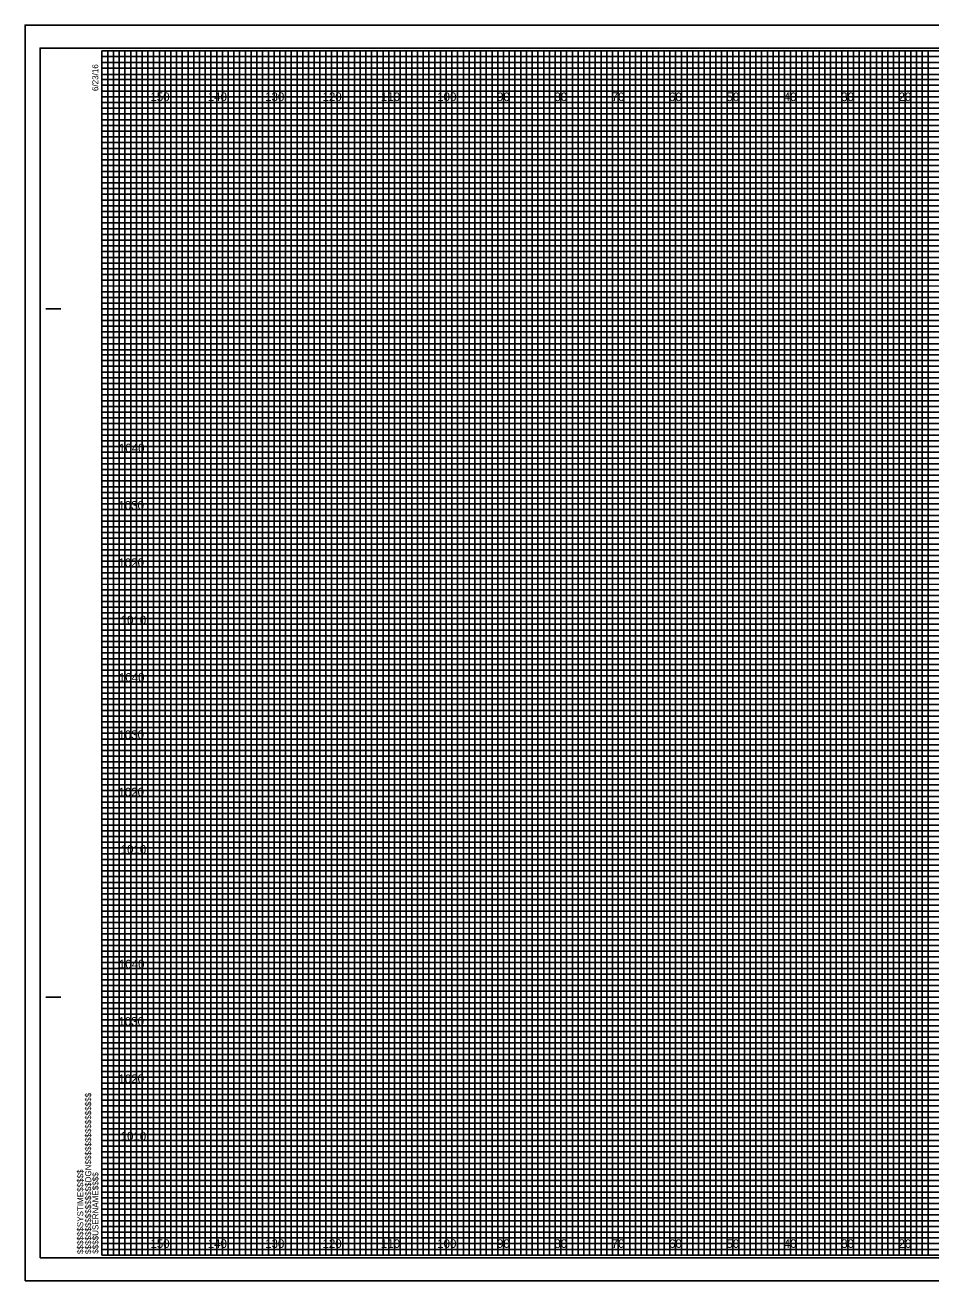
# Model space of a CAD drawing. Extents: x -13 to 323, y -5 to 215.
# Drawn here: x -13.4 to 144.5, y -4.5 to 214.5 of the extents above; entities that cross this region are included whole.
import ezdxf

# ---------------------------------------------------------------- set-up
doc = ezdxf.new("R2010")
doc.units = 0
for name, color, linetype in [('Prop XS Elevation Labels', 7, 'Continuous'), ('Prop XS Offset Labels', 7, 'Continuous'), ('Sheet Cross Section CELL', 7, 'Continuous'), ('Sheet Cross Section Grid Major CELL', 7, 'Continuous'), ('Sheet Cross Section Grid Middle CELL', 7, 'Continuous'), ('Sheet Cross Section Grid Minor 1 CELL', 7, 'Continuous'), ('Sheet Cross Section Grid Minor 2 CELL', 7, 'Continuous'), ('Sheet Cutting Line CELL', 7, 'Continuous'), ('Sheet DOT Grid CELL', 7, 'Continuous'), ('Sheet Plot Border Inside CELL', 7, 'Continuous'), ('Sheet Plot Border Outside CELL', 7, 'Continuous')]:
    doc.layers.add(name, color=color, linetype=linetype)

msp = doc.modelspace()

# ---------------------------------------------------------------- linework, layer by layer
at = {"layer": 'Sheet Cross Section CELL'}
for p, q in [((-9.8, 165), (-7.3, 165)), ((-9.7, 165), (-7.2, 165)), ((-9.8, 45), (-7.3, 45)), ((-9.7, 45), (-7.2, 45)), ((0, 0), (0, 0)), ((0, 0), (0, 0)), ((0, 0), (0, 0)), ((0, 0), (0, 0)), ((0, 0), (0, 0)), ((0, 0), (0, 0)), ((0, 0), (0, 0))]:
    msp.add_line(p, q, dxfattribs=at)
msp.add_lwpolyline([(320, 210), (0, 210), (0, 0), (320, 0)], close=True, dxfattribs=at)
at = {"layer": 'Sheet Cross Section Grid Major CELL'}
for p, q in [((10, 210), (0, 210)), ((10, 0), (10, 210)), ((30, 210), (20, 210)), ((20, 210), (20, 0)), ((30, 0), (30, 210)), ((50, 210), (40, 210)), ((40, 210), (40, 0)), ((50, 0), (50, 210)), ((70, 210), (60, 210)), ((60, 210), (60, 0)), ((70, 0), (70, 210)), ((90, 210), (80, 210)), ((80, 210), (80, 0)), ((90, 0), (90, 210)), ((110, 210), (100, 210)), ((100, 210), (100, 0)), ((110, 0), (110, 210)), ((130, 210), (120, 210)), ((120, 210), (120, 0)), ((130, 0), (130, 210)), ((150, 210), (140, 210)), ((140, 210), (140, 0)), ((20, 0), (10, 0)), ((40, 0), (30, 0)), ((60, 0), (50, 0)), ((80, 0), (70, 0)), ((100, 0), (90, 0)), ((120, 0), (110, 0)), ((140, 0), (130, 0))]:
    msp.add_line(p, q, dxfattribs=at)
for points in [[(0, 200), (320, 200), (320, 190), (0, 190)], [(0, 180), (320, 180), (320, 170), (0, 170)], [(0, 160), (320, 160), (320, 150), (0, 150)], [(0, 140), (320, 140), (320, 130), (0, 130)], [(0, 120), (320, 120), (320, 110), (0, 110)], [(0, 100), (320, 100), (320, 90), (0, 90)], [(0, 80), (320, 80), (320, 70), (0, 70)], [(0, 60), (320, 60), (320, 50), (0, 50)], [(0, 40), (320, 40), (320, 30), (0, 30)], [(0, 20), (320, 20), (320, 10), (0, 10)]]:
    msp.add_lwpolyline(points, dxfattribs=at)
at = {"layer": 'Sheet Cross Section Grid Middle CELL'}
for points in [[(0, 210), (5, 210), (5, 0), (15, 0), (15, 210), (25, 210), (25, 0), (35, 0), (35, 210), (45, 210), (45, 0), (55, 0), (55, 210), (65, 210), (65, 0), (75, 0), (75, 210), (85, 210), (85, 0), (95, 0), (95, 210), (105, 210), (105, 0), (115, 0), (115, 210), (125, 210), (125, 0), (135, 0), (135, 210), (145, 210)], [(0, 205), (275, 205)], [(0, 185), (320, 185), (320, 195), (0, 195)], [(0, 165), (320, 165), (320, 175), (0, 175)], [(0, 145), (320, 145), (320, 155), (0, 155)], [(0, 125), (320, 125), (320, 135), (0, 135)], [(0, 105), (320, 105), (320, 115), (0, 115)], [(0, 85), (320, 85), (320, 95), (0, 95)], [(0, 65), (320, 65), (320, 75), (0, 75)], [(0, 45), (320, 45), (320, 55), (0, 55)], [(0, 25), (320, 25), (320, 35), (0, 35)], [(0, 5), (320, 5), (320, 15), (0, 15)]]:
    msp.add_lwpolyline(points, dxfattribs=at)
at = {"layer": 'Sheet Cross Section Grid Minor 1 CELL'}
for p, q in [((0, 209), (260, 209)), ((260, 207.98), (0, 207.98)), ((0, 207.98), (0, 207)), ((0, 207), (260, 207)), ((260, 205.89), (0, 205.89)), ((0, 205.89), (0, 204)), ((0, 204), (320, 204))]:
    msp.add_line(p, q, dxfattribs=at)
for points in [[(0, 203), (270, 203), (320, 203), (320, 202), (0, 202)], [(0, 201), (320, 201), (320, 199), (0, 199)], [(0, 198), (320, 198), (320, 197), (0, 196.98)], [(0, 196), (320, 196), (320, 194), (0, 194)], [(0, 193), (320, 193), (320, 192), (0, 192)], [(0, 191), (320, 191), (320, 189), (0, 189)], [(0, 188), (320, 188), (320, 187), (0, 187)], [(0, 186), (320, 186), (320, 184), (0, 184)], [(0, 183), (320, 183), (320, 182), (0, 182)], [(0, 181), (320, 181), (320, 179), (0, 179)], [(0, 178), (320, 178), (320, 177), (0, 177)], [(0, 176), (320, 176), (320, 173.95), (320, 173), (320, 172), (0, 172)], [(0, 174), (320, 174), (320, 173), (0, 173)], [(0, 171), (320, 171), (320, 169), (0, 169.03)], [(0, 169.03), (320, 169), (320, 168), (0, 168)], [(0, 167), (320, 167), (320, 166), (0, 166)], [(0, 164), (320, 164), (320, 163), (0, 163)], [(0, 162), (320, 162), (320, 161), (0, 161)], [(-0.07, 158.89), (320, 158.89), (320, 157.88), (-0.07, 157.88)], [(0, 157), (320, 157), (320, 156), (0, 156)], [(0, 154), (320, 154), (320, 153), (0, 153)], [(0, 152), (320, 152), (320, 151), (0, 151)], [(0, 149), (320, 149), (320, 148), (0, 148)], [(0, 147), (320, 147), (320, 146), (0, 146)], [(0, 144), (320, 144), (320, 143), (0, 143)], [(0, 142), (320, 142), (320, 141), (0, 141)], [(0, 139), (320, 139), (319.99, 137.98), (0, 138)], [(0, 137), (320, 137), (320, 136), (0, 136)], [(0, 134), (320, 134), (320, 133), (0, 133)], [(0, 132), (320, 132), (320, 131), (0, 131)], [(0, 129), (320, 129), (320, 128), (0, 128)], [(0, 127), (320, 127), (320, 126), (0, 126)], [(0, 124), (320, 124), (320, 123), (0, 123)], [(0, 122), (320, 122), (320, 121), (0, 121)], [(0, 119), (320, 119), (320, 118), (0, 118)], [(0, 116.99), (320.07, 116.91), (320, 116), (0, 116)], [(0, 114), (320, 114), (320, 113), (0, 113)], [(0, 112), (320, 112), (320, 111), (0, 111)], [(0, 109), (320, 109), (320, 108), (0, 108)], [(0, 107), (320, 107), (320, 106), (0, 106)], [(0, 104), (320, 104), (320, 103), (0, 103)], [(0, 102), (320, 102), (320, 101), (0, 101)], [(0, 99), (320, 99), (320, 98), (0, 98)], [(0, 97), (320, 97), (320, 96), (0, 96)], [(0, 94), (320, 94), (320, 93), (0, 93)], [(0, 92), (320, 92), (320, 91), (0, 91)], [(0, 89), (320, 89), (320, 88), (0, 88)], [(0, 87), (320, 87), (320, 86), (0, 86)], [(0, 84), (320, 84), (320, 83), (0, 83)], [(0, 82), (320, 82), (320, 81), (0, 81)], [(0, 79), (320, 79), (319.99, 77.98), (0, 78)], [(0, 77), (320, 77), (320, 76), (0, 76)], [(0, 74), (320, 74), (320, 73), (0, 73)], [(0, 72), (320, 72), (320, 71), (0, 71)], [(0, 69), (320, 69), (320, 68), (0, 68)], [(0, 67), (320, 67), (320, 66), (0, 66)], [(0, 64), (320, 64), (320, 63), (0, 63)], [(0, 62), (320, 62), (320, 61), (0, 61)], [(0, 59), (320, 59), (320, 58), (0, 58)], [(0, 56.99), (320.07, 56.91), (320, 56), (0, 56)], [(0, 54), (320, 54), (320, 53), (0, 53)], [(0, 52), (320, 52), (320, 51), (0, 51)], [(0, 49), (320, 49), (320, 48), (0, 48)], [(0, 47), (320, 47), (320, 46), (0, 46)], [(0, 44), (320, 44), (320, 43), (0, 43)], [(0, 42), (320, 42), (320, 41), (0, 41)], [(0, 39), (320, 39), (320, 38), (0, 38)], [(0, 37), (320, 37), (320, 36), (0, 36)], [(0, 34), (320, 34), (320, 33), (0, 33)], [(0, 32), (320, 32), (320, 31), (0, 31)], [(0, 29), (320, 29), (320, 28), (0, 28)], [(0, 27), (320, 27), (320, 26), (0, 26)], [(0, 24), (320, 24), (320, 23), (0, 23)], [(0, 22), (320, 22), (320, 21), (0, 21)], [(0, 19), (320, 19), (320, 18), (0, 18)], [(0, 17), (320, 17), (320, 16), (0, 16)], [(0, 14), (320, 14), (320, 13), (0, 13)], [(0, 12), (320, 12), (320, 11), (0, 11)], [(0, 9), (320, 9), (320, 8), (0, 8)], [(0, 7), (320, 7), (320, 6), (0, 6)], [(0, 4), (320, 4), (320, 3), (0, 3)], [(0, 2), (320, 2), (320, 1), (0, 1)]]:
    msp.add_lwpolyline(points, dxfattribs=at)
at = {"layer": 'Sheet Cross Section Grid Minor 2 CELL'}
for points in [[(0, 0), (1, 0), (1, 210), (2, 210), (2, 0)], [(2, 0), (3, 0), (3, 210), (4, 210), (4, 0)], [(5, 0), (6, 0), (6, 210), (7, 210), (7, 0)], [(7, 0), (8, 0), (8, 210), (9, 210), (9, 0)], [(10, 0), (11, 0), (11, 210), (12, 210), (12, 0)], [(12, 0), (13, 0), (13, 210), (14, 210), (14, 0)], [(15, 0), (16, 0), (16, 210), (17, 210), (17, 0)], [(17, 0), (18, 0), (18, 210), (19, 210), (19, 0)], [(20, 0), (21, 0), (21, 210), (22, 210), (22, 0)], [(22, 0), (23, 0), (23, 210), (24, 210), (24, 0)], [(25, 0), (26, 0), (26, 210), (27, 210), (27, 0)], [(27, 0), (28, 0), (28, 210), (29, 210), (29, 0)], [(30, 0), (31, 0), (31, 210), (32, 210), (32, 0)], [(32, 0), (33, 0), (33, 210), (34, 210), (34, 0)], [(35, 0), (36, 0), (36, 210), (37, 210), (37, 0)], [(37, 0), (38, 0), (38, 210), (39, 210), (39, 0)], [(40, 0), (41, 0), (41, 210), (42, 210), (42, 0)], [(42, 0), (43, 0), (43, 210), (44, 210), (44, 0)], [(45, 0), (46, 0), (46, 210), (47, 210), (47, 0)], [(47, 0), (48, 0), (48, 210), (49, 210), (49, 0)], [(50, 0), (51, 0), (51, 210), (52, 210), (52, 0)], [(52, 0), (53, 0), (53, 210), (54, 210), (54, 0)], [(55, 0), (56, 0), (56, 210), (57, 210), (57, 0)], [(57, 0), (58, 0), (58, 210), (59, 210), (59, 0)], [(60, 0), (61, 0), (61, 210), (62, 210), (62, 0)], [(62, 0), (63, 0), (63, 210), (64, 210), (64, 0)], [(65, 0), (66, 0), (66, 210), (67, 210), (67, 0)], [(67, 0), (68, 0), (68, 210), (69, 210), (69, 0)], [(70, 0), (71, 0), (71, 210), (72, 210), (72, 0)], [(72, 0), (73, 0), (73, 210), (74, 210), (74, 0)], [(75, 0), (76, 0), (76, 210), (77, 210), (77, 0)], [(77, 0), (78, 0), (78, 210), (79, 210), (79, 0)], [(80, 0), (81, 0), (81, 210), (82, 210), (82, 0)], [(82, 0), (83, 0), (83, 210), (84, 210), (84, 0)], [(85, 0), (86, 0), (86, 210), (87, 210), (87, 0)], [(87, 0), (88, 0), (88, 210), (89, 210), (89, 0)], [(90, 0), (91, 0), (91, 210), (92, 210), (92, 0)], [(92, 0), (93, 0), (93, 210), (94, 210), (94, 0)], [(95, 0), (96, 0), (96, 210), (97, 210), (97, 0)], [(97, 0), (98, 0), (98, 210), (99, 210), (99, 0)], [(100, 0), (101, 0), (101, 210), (102, 210), (102, 0)], [(102, 0), (103, 0), (103, 210), (104, 210), (104, 0)], [(105, 0), (106, 0), (106, 210), (107, 210), (107, 0)], [(107, 0), (108, 0), (108, 210), (109, 210), (109, 0)], [(110, 0), (111, 0), (111, 210), (112, 210), (112, 0)], [(112, 0), (113, 0), (113, 210), (114, 210), (114, 0)], [(115, 0), (116, 0), (116, 210), (117, 210), (117, 0)], [(117, 0), (118, 0), (118, 210), (119, 210), (119, 0)], [(120, 0), (121, 0), (121, 210), (122, 210), (122, 0)], [(122, 0), (123, 0), (123, 210), (124, 210), (124, 0)], [(125, 0), (126, 0), (126, 210), (127, 210), (127, 0)], [(127, 0), (128, 0), (128, 210), (129, 210), (129, 0)], [(130, 0), (131, 0), (131, 210), (132, 210), (132, 0)], [(132, 0), (133, 0), (133, 210), (134, 210), (134, 0)], [(135, 0), (136, 0), (136, 210), (137, 210), (137, 0)], [(137, 0), (138, 0), (138, 210), (139, 210), (139, 0)], [(140, 0), (141, 0), (141, 210), (142, 210), (142, 0)], [(142, 0), (143, 0), (143, 210), (144, 210), (144, 0)]]:
    msp.add_lwpolyline(points, dxfattribs=at)
at = {"layer": 'Sheet Cutting Line CELL'}
for p, q in [((323.3, 214.5), (-13.4, 214.5)), ((-13.4, 214.5), (-13.4, -4.5)), ((-13.4, -4.5), (323.3, -4.5))]:
    msp.add_line(p, q, dxfattribs=at)
at = {"layer": 'Sheet DOT Grid CELL'}
for p, q in [((10, 0), (10, 210)), ((20, 0), (20, 210)), ((30, 0), (30, 210)), ((40, 0), (40, 210)), ((50, 0), (50, 210)), ((60, 0), (60, 210)), ((70, 0), (70, 210)), ((80, 0), (80, 210)), ((90, 0), (90, 210)), ((100, 0), (100, 210)), ((110, 0), (110, 210)), ((120, 0), (120, 210)), ((130, 0), (130, 210)), ((140, 0), (140, 210)), ((0, 200), (320, 200)), ((0, 190), (320, 190)), ((0, 180), (320, 180)), ((0, 170), (320, 170)), ((0, 160), (320, 160)), ((0, 150), (320, 150)), ((0, 140), (320, 140)), ((0, 130), (320, 130)), ((0, 120), (320, 120)), ((0, 110), (320, 110)), ((0, 100), (320, 100)), ((0, 90), (320, 90)), ((0, 80), (320, 80)), ((0, 70), (320, 70)), ((0, 60), (320, 60)), ((0, 50), (320, 50)), ((0, 40), (320, 40)), ((0, 30), (320, 30)), ((0, 20), (320, 20)), ((0, 10), (320, 10))]:
    msp.add_line(p, q, dxfattribs=at)
at = {"layer": 'Sheet Plot Border Inside CELL'}
msp.add_lwpolyline([(-10.8, -0.5), (322.4, -0.5), (322.4, 210.5), (-10.8, 210.5)], close=True, dxfattribs=at)
at = {"layer": 'Sheet Plot Border Outside CELL'}
msp.add_lwpolyline([(-13.4, -4.5), (323.3, -4.5), (323.3, 214.5), (-13.4, 214.5)], close=True, dxfattribs=at)

# ---------------------------------------------------------------- texts
at = {"layer": 'Prop XS Elevation Labels'}
for s, p in [('1040', (2.95, 140)), ('1030', (2.86, 130)), ('1020', (2.87, 120)), ('1010', (3.25, 110)), ('1040', (2.95, 100)), ('1030', (2.86, 90)), ('1020', (2.87, 80)), ('1010', (3.25, 70)), ('1040', (2.95, 50)), ('1030', (2.86, 40)), ('1020', (2.87, 30)), ('1010', (3.25, 20))]:
    msp.add_text(s, height=1.5, dxfattribs=at).set_placement(p)
at = {"layer": 'Prop XS Offset Labels'}
for s, p in [('150', (8.44, 201.25)), ('140', (18.44, 201.25)), ('130', (28.44, 201.25)), ('120', (38.44, 201.25)), ('110', (48.62, 201.25)), ('100', (58.44, 201.25)), ('90', (68.86, 201.25)), ('80', (78.86, 201.25)), ('70', (88.86, 201.25)), ('60', (98.86, 201.25)), ('50', (108.86, 201.25)), ('40', (118.86, 201.25)), ('30', (128.86, 201.25)), ('20', (138.86, 201.25)), ('150', (8.44, 1.25)), ('140', (18.44, 1.25)), ('130', (28.44, 1.25)), ('120', (38.44, 1.25)), ('110', (48.62, 1.25)), ('100', (58.44, 1.25)), ('90', (68.86, 1.25)), ('80', (78.86, 1.25)), ('70', (88.86, 1.25)), ('60', (98.86, 1.25)), ('50', (108.86, 1.25)), ('40', (118.86, 1.25)), ('30', (128.86, 1.25)), ('20', (138.86, 1.25))]:
    msp.add_text(s, height=1.5, dxfattribs=at).set_placement(p)
at = {"layer": 'Sheet Cross Section CELL'}
for s, p in [('6/23/16', (-0.65, 203)), ('$$$$$$$$$$$$$$$$DGN$$$$$$$$$$$$$$$$', (-1.88, 0.18)), ('$$$$$$SYSTIME$$$$$', (-3.26, 0.18)), ('$$$$USERNAME$$$$', (-0.62, 0.23))]:
    msp.add_text(s, height=1.05, rotation=90, dxfattribs=at).set_placement(p)

doc.saveas('drawing.dxf')
